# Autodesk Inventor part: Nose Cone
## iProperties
Shininess: 20.0
Angle Display Precision: 2
Document Length Units: 11269
Document Angle Units: 11279
Document Time Units: 11290
Document Mass Units: 11283
Document Length Units Precision: 3
Document Angle Units Precision: 2
Compacted: True
Created: 2001-08
Part Number: Nose Cone
Document SubType Name: Modeling
Designer: Martin Budgell
Density: 0.0
Volumn: 0.0
Area: 0.0
PropertySet Name: Model Information
Control State: 0
Master: False
Checked Out: False
Author: Martin Budgell
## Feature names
1. Extrusion1
2. Extrusion2
3. Extrusion3
4. Fillet1
5. Extrusion4
6. Fillet2
7. Fillet3
8. Fillet4
9. Fillet5
10. Fillet6
11. Fillet7
12. Shell1
13. Fillet8
14. Extrusion5
15. Fillet9
16. Extrusion6
17. Chamfer1
